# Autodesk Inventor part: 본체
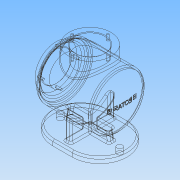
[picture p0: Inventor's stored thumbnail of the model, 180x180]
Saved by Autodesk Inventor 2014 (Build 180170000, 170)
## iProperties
Created: 2016-04
Part Number: 본체
Material: 알루미늄 6061
Document SubType Name: Modeling
Designer: 601-
Density: 2.71 g/cm^3
Appearance: 알루미늄 - 평지
Mass: 948.525 g
Surface Area: 1271.5 cm^2
Volume: 350.009 cm^3
Author: 601-
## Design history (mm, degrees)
sketch "스케치1"
  geometry: L1 (67.5, -50)-(-67.5, -50); L2 (-67.5, -50)-(-67.5, 50); L3 (-67.5, 50)-(67.5, 50); L4 (67.5, 50)-(67.5, -50); L5 (67.5, -50)-(-67.5, 50); L6 (-67.5, -50)-(67.5, 50); L7 (-17.5, 50)-(-17.5, -50); L8 (17.5, 50)-(17.5, -50); L9 (-17.5, 50)-(17.5, 50); L10 (-17.5, -50)-(17.5, -50); 5 further points; 2 other entities
  constraints: 20 end point, 7 horizontal, 5 midpoint, 4 point on line, 3 perpendicular, 2 parallel, 1 coincident, 1 vertical, 8 other
  dimensions: "d0" = 135 distance of L2.end L3.end; "d1" = 100 distance of L3.end L1.start; "d2" = 50 distance between parallel lines of L2 L7; "d3" = 50 distance between parallel lines of L4 L8
extrude "돌출1" new body sketch "스케치1" distance "d4" = 10; taper "d5" = 0 deg
sketch "스케치6"
  geometry: L1 (-17.5, 10)-(-67.5, 10) reference; L2 (67.5, 10)-(17.5, 10) reference; L3 (-17.5, 10)-(17.5, 10) reference; L4 (-40, 10)-(-26.07, 89); L5 (-26.07, 89)-(26.07, 89); L6 (26.07, 89)-(40, 10); L7 (0, 0)-(0, 30.754)
  constraints: 8 end point, 2 point on line, 1 parallel, 1 perpendicular
  dimensions: "d15" = 40 distance from line of L4.start L7; "d16" = 40 distance from line of L6.end L7; "d17" = 100 deg angle of L2 L6; "d18" = 100 deg angle of L1 L4; "d19" = 79 distance between parallel lines of L2 L5
extrude "돌출2" join sketch "스케치6" stored distance "d20" = 10; taper "d21" = 0 deg
sketch "스케치7"
  geometry: L1 (-40, 10)-(-40, 89); L2 (-40, 89)-(40, 89); L3 (40, 89)-(40, 10); L4 (50, 0)-(-50, 0) reference; L5 (-40, 10)-(40, 10); 2 further points
  constraints: 8 end point, 1 coincident, 1 parallel, 1 perpendicular
  dimensions: "d22" = 40 distance from line of point (0, 0) L1; "d23" = 40 distance from line of point (0, 0) L3; "d24" = 89 distance between parallel lines of L4 L2
extrude "돌출3" join sketch "스케치7" stored distance "d25" = 10; taper "d26" = 0 deg
sketch "스케치8"
  geometry: L1 (50, 79)-(-50, 79); L2 (-50, 79)-(-50, 129); L3 (-50, 129)-(50, 129); L4 (50, 129)-(50, 79); L5 (50, 79)-(-50, 129); L6 (-50, 79)-(50, 129); L7 (-17.5, 0)-(-67.5, 0) reference; L8 (-17.5, 0)-(17.5, 0) reference; 4 further points
  constraints: 12 end point, 4 midpoint, 2 parallel, 1 horizontal, 1 perpendicular, 1 vertical alignment
  dimensions: "d27" = 79 distance between parallel lines of L7 L1; "d29" = 100 diameter of L3 L1; "d30" = 100 distance of L2.end L3.end
revolve "회전1" sketch "스케치8" stored, may be unused: angle "d31" = 90 deg
sketch "스케치9"
  geometry: C1 r 50 at (0, 0) reference; C2 r 38 at (0, 0); 1 further point
  constraints: 1 centre point, 1 coincident
  dimensions: "d32" = 76 diameter of C2
extrude "돌출4" join sketch "스케치9" distance "d33" = 12; taper "d34" = 0 deg
sketch "스케치10"
  geometry: L1 (17.5, 0)-(-17.5, 0) reference; L2 (-38, 129)-(-38, 144); L3 (-38, 144)-(0, 144); L4 (0, 144)-(0, 129); L5 (-17.5, 0)-(-67.5, 0) reference; L6 (-38, 129)-(-38, 98.072); L7 (-50, 129)-(50, 129) reference; L8 (-38, 98.072)-(0, 98.072); L9 (0, 98.072)-(0, 129); 2 further points
  constraints: 12 end point, 2 parallel, 2 perpendicular, 1 midpoint
  dimensions: "d37" = 76 diameter of L2 L4; "d38" = 144 distance between parallel lines of L5 L3
revolve "회전2" sketch "스케치10" stored, may be unused: angle "d39" = 90 deg
sketch "스케치11"
  geometry: 3 further points
  dimensions: "d40" = 54 distance of point (0, 0) point (-54, 0); "d41" = 54 distance of point (0, 0) point (54, 0)
hole "구멍1" sketch "스케치11" at (-54, 0), (54, 0) diameter "d42" = 10; stored, may be unused: countersink angle "d46" = 90 deg, drill point angle "d48" = 118 deg; dims "d43" = 6, "d44" = 4, "d45" = 2, "d47" = 8
sketch "스케치12" dims "d49" = 65
  geometry: C1 r 38 at (0, 0) reference; 3 further points
  constraints: 1 coincident, 1 vertical alignment, 2 other
hole "구멍2" sketch "스케치12" at (0, 32.5) diameter "d50" = 3.242; stored, may be unused: countersink angle "d54" = 90 deg, drill point angle "d56" = 118 deg; dims "d51" = 8, "d52" = 4, "d53" = 2, "d55" = 10
chamfer "모따기1" distance "d60" = 3; stored, may be unused: second distance "d61" = 2, angle "d62" = 45 deg
fillet "모깎기1" dims "d63" = 3
fillet "모깎기2" dims "d64" = 3, "d92" = 5
sketch "스케치13"
  geometry: L1 (-60.257, 79)-(59.743, 79); L2 (67.5, 0)-(17.5, 0) reference; L3 (-50, 129)-(-50, 29); L4 (-60.257, 79)-(-50, 79); L5 (-50, 29)-(-50, 129) reference; L6 (-50, 129)-(-50, 79); A1 r 127 centre (66.743, 79) between (-50, 129) and (-50, 29); 1 further point
  constraints: 8 end point, 3 point on circle, 1 centre point, 1 collinear, 1 midpoint
  dimensions: "d70" = 120 distance of L1.start L1.end; "d72" = 79 distance between parallel lines of L2 L1; "d112" = 127 radius of A1
revolve "회전3" sketch "스케치13" stored, may be unused: angle "d69" = 90 deg
sketch "스케치15"
  geometry: L1 (-50, 129)-(45, 129) reference; L2 (-48.004, 126)-(47, 126); L3 (-57.257, 79)-(44.743, 79); L4 (47, 126)-(47, 79); L5 (47, 79)-(44.743, 79); L6 (50, 38)-(50, 120) reference; A1 r 127 centre (66.743, 79) between (-50, 129) and (-50, 29) reference; A2 r 124 centre (66.743, 79) between (-48.004, 126) and (-57.257, 79); 1 further point
  constraints: 8 end point, 2 parallel, 2 perpendicular, 2 point on circle, 1 centre point
  dimensions: "d73" = 3 radial gap between concentric circles of A1 A2; "d74" = 3 distance between parallel lines of L1 L2; "d111" = 3 distance from line of L6 L4.end
revolve "회전4" sketch "스케치15" stored, may be unused: angle "d75" = 90 deg
sketch "스케치16"
  geometry: C1 r 38 at (0, 0) reference; 1 further point
hole "구멍3" sketch "스케치16" at (0, 0) diameter "d76" = 54; stored, may be unused: countersink angle "d80" = 90 deg, drill point angle "d82" = 0 deg; dims "d77" = 8, "d78" = 4, "d79" = 2, "d81" = 30
sketch "스케치17"
  geometry: C1 r 38 at (0, 0) reference
hole "구멍4" sketch "스케치17" at (0, 0) diameter "d83" = 54; stored, may be unused: countersink angle "d87" = 90 deg, drill point angle "d89" = 0 deg; dims "d84" = 8, "d85" = 4, "d86" = 2, "d88" = 50
fillet "모깎기3" dims "d90" = 5, "d91" = 2
chamfer "모따기2" distance "d93" = 1; stored, may be unused: second distance "d94" = 2, angle "d95" = 45 deg
sketch "스케치18"
  geometry: C1 r 38 at (0, 0) reference; 1 further point
  dimensions: "d96" = 32.5 distance of C1.centre point (0, 32.5)
hole "구멍5" sketch "스케치18" at (0, 32.5) diameter "d97" = 3.242; stored, may be unused: countersink angle "d101" = 90 deg, drill point angle "d103" = 118 deg; dims "d98" = 8, "d99" = 4, "d100" = 2, "d102" = 10
node "작업 평면1"
sketch "스케치20"
  geometry: 2 further points
  constraints: 1 vertical alignment, 1 other
  dimensions: "d108" = 79 distance of point (0, 0) point (0, 79)
feature "엠보싱1" sketch "스케치20" dims "d0" = 135, "d1" = 100, "d2" = 50, "d3" = 50, "d109" = 0.5, "d110" = 0
node "솔리드1"
pattern_circular "원형 패턴1" dims angle "d58" = 360 deg
pattern_circular "원형 패턴2" dims angle "d105" = 360 deg
